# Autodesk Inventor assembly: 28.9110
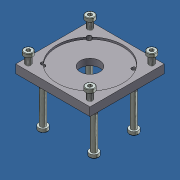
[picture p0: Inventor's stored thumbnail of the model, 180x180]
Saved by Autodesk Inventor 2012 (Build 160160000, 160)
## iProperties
Created: 2013-11
Part Number: 28.9110
Document SubType Name: Assembly
Designer: Admin
Description: ADAPTOR PLATE LR6-NEMA 34
FINISH: MILL FINISH
Author: Admin
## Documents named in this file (5)
- C:\Andys Backup Data\ANDY'S INVENTOR\INVENTOR LIBRARIES\PARTS LIBRARY\READY FOR USE MODULES LR\28.9110ADAPTOR PLATE LR6-NEMA 34.iam
- 28.9110 ADAPTOR PLATE LR6-NEMA 34.iam
- C:\Andys Backup Data\ANDY'S INVENTOR\INVENTOR LIBRARIES\PARTS LIBRARY\READY FOR USE MODULES LR\SUBCOMPONENTS\28.9110_1 ADAPTOR PLATE LR6-NEMA 34.ipt
- C:\Andys Backup Data\ANDY'S INVENTOR\INVENTOR LIBRARIES\PARTS LIBRARY\FASTENING ELEMENTS\SCREWS CAP\21.1248 M6X55.ipt
- C:\Andys Backup Data\ANDY'S INVENTOR\INVENTOR LIBRARIES\PARTS LIBRARY\FASTENING ELEMENTS\SCREWS CAP\21.1238 M6X16.ipt
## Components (9 placed, 3 different names)
1. 28.9110_1 ADAPTOR PLATE LR6-NEMA 34:1 — Insert:3, Insert:4, Insert:5, Insert:6, Insert:7, Insert:8, Insert:9, Insert:10
2. 21.1248 M6X55:2 — Insert:6
3. 21.1248 M6X55:1 — Insert:5
4. 21.1248 M6X55:3 — Insert:3
5. 21.1248 M6X55:4 — Insert:4
6. 21.1238  M6X16 SHCS:1 — Insert:7
7. 21.1238  M6X16 SHCS:2 — Insert:8
8. 21.1238  M6X16 SHCS:3 — Insert:9
9. 21.1238  M6X16 SHCS:4 — Insert:10
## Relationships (8: Insert 8)
- Insert:3: 28.9110_1 ADAPTOR PLATE LR6-NEMA 34:1 ↔ 21.1248 M6X55:3
- Insert:4: 28.9110_1 ADAPTOR PLATE LR6-NEMA 34:1 ↔ 21.1248 M6X55:4
- Insert:5: 28.9110_1 ADAPTOR PLATE LR6-NEMA 34:1 ↔ 21.1248 M6X55:1
- Insert:6: 28.9110_1 ADAPTOR PLATE LR6-NEMA 34:1 ↔ 21.1248 M6X55:2
- Insert:7: 28.9110_1 ADAPTOR PLATE LR6-NEMA 34:1 ↔ 21.1238  M6X16 SHCS:1
- Insert:8: 28.9110_1 ADAPTOR PLATE LR6-NEMA 34:1 ↔ 21.1238  M6X16 SHCS:2
- Insert:9: 28.9110_1 ADAPTOR PLATE LR6-NEMA 34:1 ↔ 21.1238  M6X16 SHCS:3
- Insert:10: 28.9110_1 ADAPTOR PLATE LR6-NEMA 34:1 ↔ 21.1238  M6X16 SHCS:4
